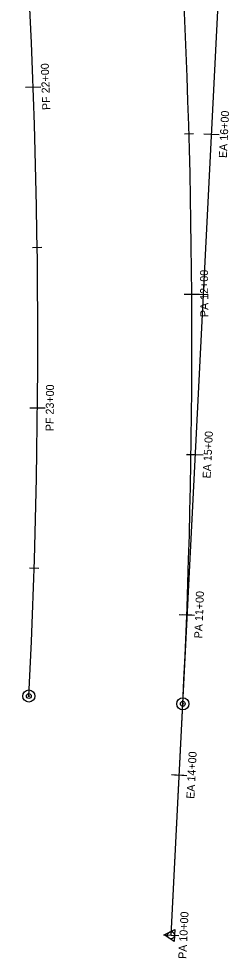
# Model space of a CAD drawing. Extents: x 950864 to 953360, y 1126381 to 1128045.
# Drawn here: x 952051.2 to 952116.7, y 1126381.5 to 1126674.4 of the extents above; entities that cross this region are included whole.
import ezdxf

# ---------------------------------------------------------------- set-up
doc = ezdxf.new("R2010")
doc.units = 0
doc.layers.add('Existing', color=7, linetype='Continuous')
doc.layers.add('Proposed', color=7, linetype='Continuous')

msp = doc.modelspace()

# ---------------------------------------------------------------- linework, layer by layer
at = {"layer": 'Existing'}
msp.add_line((952098.59, 1126388.66), (952115.99, 1126732.93), dxfattribs=at)
for points in [[(952108.81, 1126638.49), (952113.6, 1126638.25)], [(952107.25, 1126588.5), (952110.12, 1126588.36)], [(952103.76, 1126538.62), (952108.56, 1126538.37)], [(952102.2, 1126488.63), (952105.08, 1126488.49)], [(952098.72, 1126438.74), (952103.51, 1126438.5)], [(952096.41, 1126388.77), (952099.78, 1126390.49)], [(952099.78, 1126390.49), (952099.59, 1126386.71)], [(952099.59, 1126386.71), (952096.41, 1126388.77)]]:
    msp.add_lwpolyline(points, dxfattribs=at)
msp.add_circle((952098.59, 1126388.66), 1.09, dxfattribs=at)
at = {"layer": 'Proposed'}
msp.add_line((952098.59, 1126388.66), (952102.23, 1126460.8), dxfattribs=at)
for points in [[(952058.06, 1126653.06), (952053.26, 1126652.88)], [(952102.72, 1126638.47), (952105.6, 1126638.55)], [(952058.34, 1126603.01), (952055.46, 1126602.97)], [(952102.64, 1126588.5), (952107.44, 1126588.53)], [(952059.39, 1126552.96), (952054.59, 1126553.01)], [(952103.37, 1126538.54), (952106.25, 1126538.49)], [(952057.38, 1126502.95), (952054.5, 1126503.05)], [(952101.07, 1126488.63), (952105.86, 1126488.45)], [(952099.67, 1126438.66), (952102.55, 1126438.52)], [(952096.41, 1126388.77), (952099.78, 1126390.49)], [(952099.78, 1126390.49), (952099.59, 1126386.71)], [(952096.19, 1126388.78), (952100.99, 1126388.53)], [(952099.59, 1126386.71), (952096.41, 1126388.77)]]:
    msp.add_lwpolyline(points, dxfattribs=at)
for centre, radius in [((952054.29, 1126463.22), 1.89), ((952054.29, 1126463.22), 0.744), ((952054.29, 1126463.22), 0.154), ((952102.23, 1126460.8), 1.88), ((952102.23, 1126460.8), 0.747), ((952102.23, 1126460.8), 0.156), ((952098.59, 1126388.66), 1.09)]:
    msp.add_circle(centre, radius, dxfattribs=at)
for radius, end in [(2240, 9.4135), (2192, 4.20829)]:
    msp.add_arc((949865.09, 1126573.85), radius, 357.10692, end, dxfattribs=at)

# ---------------------------------------------------------------- texts
at = {"layer": 'Existing'}
for s, p in [('EA 16+00', (952115.93, 1126630.91)), ('EA 15+00', (952110.88, 1126531.02)), ('EA 14+00', (952105.83, 1126431.14))]:
    msp.add_text(s, height=2.496, rotation=87.1069, dxfattribs=at).set_placement(p)
at = {"layer": 'Proposed'}
for s, rotation, p in [('PF 22+00', 92.0684, (952061.01, 1126645.96)), ('PA 12+00', 90.375, (952110.18, 1126581.36)), ('PF 23+00', 89.4546, (952062.01, 1126545.78)), ('PA 11+00', 87.8172, (952108.27, 1126481.16)), ('PA 10+00', 87.1069, (952103.31, 1126381.22))]:
    msp.add_text(s, height=2.496, rotation=rotation, dxfattribs=at).set_placement(p)

doc.saveas('drawing.dxf')
